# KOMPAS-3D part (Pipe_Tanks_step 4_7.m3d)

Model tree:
1. X Axis
2. Y Axis
3. Z Axis  (labels: T-Bend Dn 150; Pipe Dn 150)
     Òîëùèíà ñòåíêè 1 = 1

Referenced files in C:\Documents and Settings\kashirsky\Мои документы\Camtasia Studio\Pipelines3D\Tanks\: Tanks_step 4.a3d
Referenced files in C:\Program Files\ASCON\KOMPAS-3D V10\Libs\Piping\LOAD\: Piping_C_Pipe_150_1000.m3d
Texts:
  Pipe Dn 150
  Steel ASTM A295
  Three Point Plane
  Plane at Angle
  Line and Point Plane
  Axis through Two Vertices
  Axis of Feature
  Axis of Conical Surface
  Axis through Edge
  Trim by Surface
  Trim by Sketch
  Feature with No History
  Intersection Axis of Two Planes
  Two Line Plane
  Line and Face Plane
  Bend by line
  Hole in sheet body
  Cut in sheet body
  Point in CM
  Linear Dimension from Line to Point
  Surface Finish Symbol
  Geometric Tolerance Symbol
  Leader #1
  Leader #2
  Leader #3
  Shape Deviations and Datum
  Node point number
  Mark of coordination axis
  Node point designation
  Mark/Reference designation with leader
  Mark/reference designation on line
  Mark/Reference designation without leader
  T-Bend Dn 150
  Plane of section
